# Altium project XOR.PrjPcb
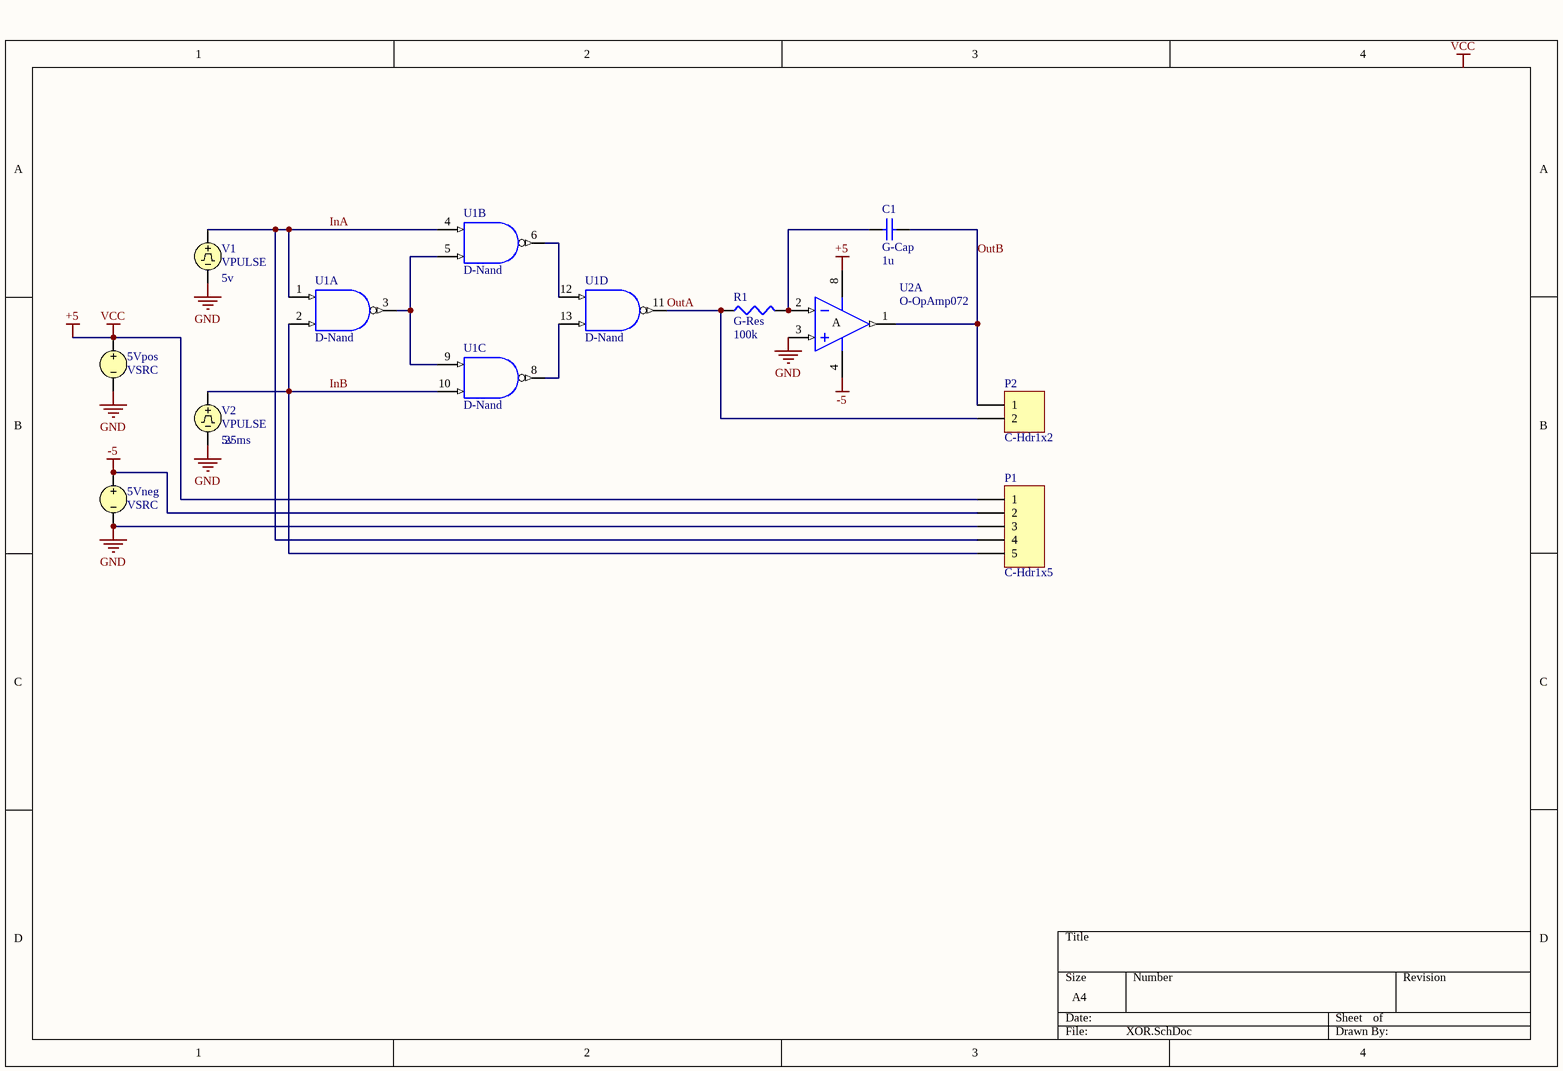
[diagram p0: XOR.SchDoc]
1 sheet, 10 parts. Net scope: global (net labels, ports and power ports of the same name join across sheets).

## Sheet XOR.SchDoc
size A4

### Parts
5Vneg  VSRC
5Vpos  VSRC
C1  G-Cap  value 1u  [Cap2.1cm_LGE1.0]
P1  C-Hdr1x5  [HDR1X5_LGE1.0]
P2  C-Hdr1x2  [HDR1X2_LGE1.0]
R1  G-Res  value 100k  [Res2.54mm_LGE1.0]
U1  D-Nand  [DIP14_LGE1.0]  (parts A,B,C,D of 4)
U2  O-OpAmp072  [DIP8_SML0.8]  (part A of 2)
V1  VPULSE  Pulsed Value: 5v
V2  VPULSE  Pulsed Value: 5v  Time Delay: .25ms

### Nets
+5: 5Vpos.1 P1.1 U1.14(VCC) U2.8(V+)  [also labelled VCC]
-5: 5Vneg.1 P1.2 U2.4(V-)
GND: 5Vneg.2 5Vpos.2 P1.3 U1.7(GND) U2.3(IN+) V1.2 V2.2
InA: P1.4 U1.1(A) U1.4(A) V1.1
InB: P1.5 U1.2(B) U1.10(B) V2.1
OutA: P2.2 R1.1 U1.11(Y)
OutB: C1.2 P2.1 U2.1(OUT)
NetC1_1: C1.1 R1.2 U2.2(IN-)
NetU1_3: U1.3(Y) U1.5(B) U1.9(A)
NetU1_6: U1.6(Y) U1.12(A)
NetU1_8: U1.8(Y) U1.13(B)

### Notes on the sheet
- Labels drawn without touching a wire or pin: VCC

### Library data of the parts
5Vneg = VSRC: Voltage Source; Note: PCB Footprint - Not required; Value: -5
5Vpos = VSRC: Voltage Source; Note: PCB Footprint - Not required; Value: +5
C1 = G-Cap: capacitor (specify value)
P1 = C-Hdr1x5: Header, 6-Pin
P2 = C-Hdr1x2: Header, 2-Pin
R1 = G-Res: resistor (specify value)
U1 = D-Nand: quad 2-input NAND gate
U2 = O-OpAmp072: op amp (TL072)
V1 V2 = VPULSE: Pulse Voltage Source; Note: PCB Footprint - Not required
